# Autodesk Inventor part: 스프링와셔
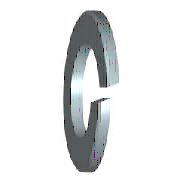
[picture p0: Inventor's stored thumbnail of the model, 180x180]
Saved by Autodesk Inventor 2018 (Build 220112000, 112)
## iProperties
IsCustomPart: 1
Created: 2012-02
Part Number: 스프링와셔
Material: 강철, 연강
Description: 스프링 와셔
Document SubType Name: Modeling
Standard: JIS B 1251
Designer: mduedu
Standards Organization: JIS
Language: ko-KR
Size Designation: 번호 2 4
Categories: <MemberInstance><Categories><Category DisplayName="조임쇠" InternalName="e4da775c-781d-43d5-af7c-5136215cf5a6" Mnemonic="FSTN"><Category DisplayName="와셔" InternalN
Density: 1 g/cm^3
Appearance: 파란색 - 벽 페인트 - 광택
Author: mduedu
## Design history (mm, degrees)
sketch "스케치1"
  geometry: C1 r 3.8 at (0, 0); C2 r 2.05 at (0, 0); 1 further point
  constraints: 2 centre point, 2 coincident
  dimensions: "d0" = 4.1 diameter of C2 (= SD1); "d1" = 7.6 diameter of C1 (= SD2)
extrude "본체" new body sketch "스케치1" distance "d2" = 1 (= SD); taper "d3" = 0 deg
sketch "스케치2"
  geometry: L1 (0, -2.05)-(0, 2.05) reference; L2 (1, 3.8)-(1, -3.8) reference; L3 (-1.2, 0)-(7.2, 0) reference; L4 (0, -0.2)-(1, 0.164); L5 (0, 0.2)-(1, 0.564)
  constraints: 4 end point, 4 point on line, 1 parallel
  dimensions: "d4" = 0.2 distance from line of L3 L4.start (= 0.2 x SD); "d5" = 0.2 distance from line of L3 L5.start (= 0.2 x SD); "d6" = 70 deg angle of L2 L4 (= FAWI)
extrude "절단부" cut sketch "스케치2" stored distance "d7" = 1 (= SD); taper "d8" = 0 deg
workaxis "Work Axis1"
workplane "Work Plane1"
body "Solid1"
other parameters: "SD1" = 4.1 [user parameter; used in 1 equation term], "SD2" = 7.6 [user parameter; used in 1 equation term], "SD" = 1 [user parameter; used in 4 equation terms], "FAWI" = 70 deg [user parameter; used in 1 equation term], "d9" = 0, "d10" = 0, "d11" = 0, "d12" = 0, "SDI" = 1.4 [user parameter], "NND" = 4 [user parameter]
